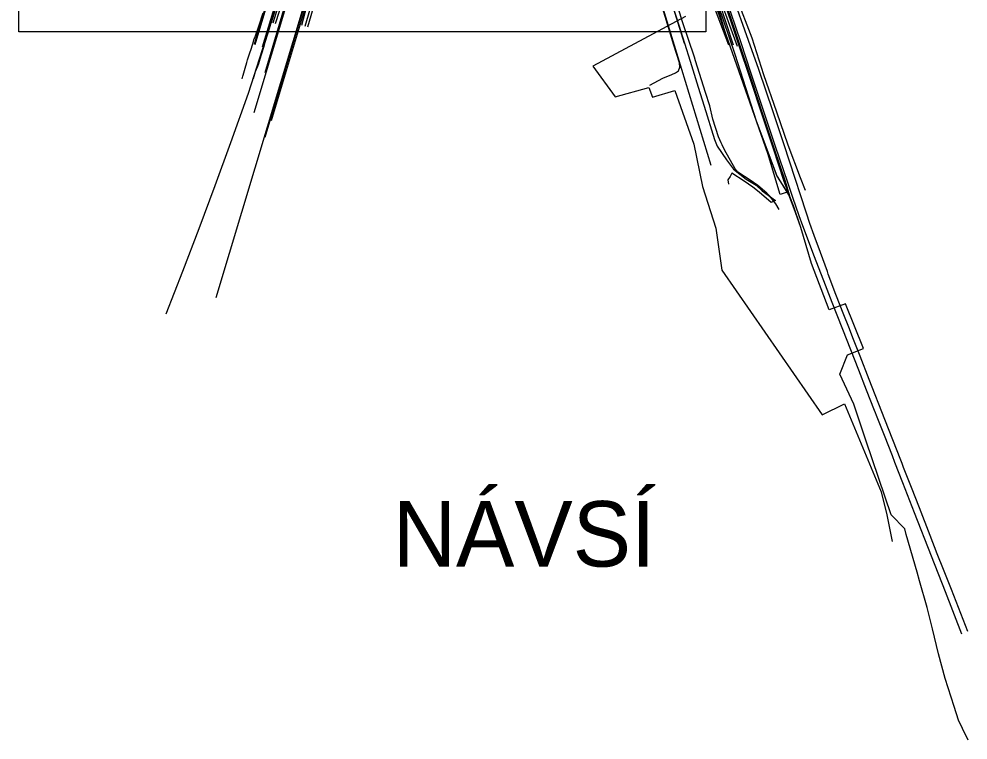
# Model space of a CAD drawing. Extents: x -439827 to -439102, y -1131353 to -1129707.
# Drawn here: x -439827 to -439102, y -1131353 to -1130802 of the extents above; entities that cross this region are included whole.
import ezdxf

# ---------------------------------------------------------------- set-up
doc = ezdxf.new("R2010")
doc.units = 0
for name, color, linetype in [('Vrstva 1', 7, 'Continuous'), ('Vrstva 11', 7, 'Continuous'), ('Vrstva 20', 7, 'Continuous'), ('Vrstva 23', 7, 'Continuous'), ('Vrstva 34', 7, 'Continuous'), ('Vrstva 4', 7, 'Continuous'), ('Vrstva 5', 7, 'Continuous'), ('Vrstva 52', 7, 'Continuous'), ('Vrstva 57', 7, 'Continuous'), ('Vrstva 59', 7, 'Continuous'), ('Vrstva 63', 7, 'Continuous'), ('Vrstva 9', 7, 'Continuous')]:
    doc.layers.add(name, color=color, linetype=linetype)

msp = doc.modelspace()

# ---------------------------------------------------------------- linework, layer by layer
at = {"layer": 'Vrstva 1'}
msp.add_lwpolyline([(-439827.03, -1130069.63), (-439302.03, -1130069.63), (-439302.03, -1130812.13), (-439827.03, -1130812.13)], close=True, dxfattribs=at)
at = {"layer": 'Vrstva 11'}
for points in [[(-439344.75, -1130853.04), (-439334.81, -1130847.64), (-439327.91, -1130844.88), (-439325.14, -1130843.49), (-439322.82, -1130841.93), (-439321.71, -1130839.17), (-439322.18, -1130835.79), (-439326.59, -1130821.58), (-439331.18, -1130806.33), (-439334.82, -1130794.63), (-439341.65, -1130772.25), (-439347.37, -1130754.14), (-439353.24, -1130735.38), (-439356.7, -1130724.07), (-439358.88, -1130721.3), (-439364.23, -1130721.5)], [(-439327.41, -1130792.13), (-439322.68, -1130807.07), (-439318.32, -1130820.97), (-439314.01, -1130834.57), (-439307.87, -1130854.41), (-439303.31, -1130869.12), (-439295.3, -1130894.58), (-439293.28, -1130899.6), (-439286.23, -1130909.99), (-439280.74, -1130917.07), (-439271.1, -1130924.86), (-439263.44, -1130929.41), (-439258.82, -1130933.64), (-439248.69, -1130941.16), (-439251.96, -1130942.7), (-439261.16, -1130934.64), (-439265.96, -1130930.97), (-439272.69, -1130926.31), (-439281.98, -1130920.15), (-439283.47, -1130922.78), (-439285.1, -1130925.34), (-439284.68, -1130928.58)]]:
    msp.add_lwpolyline(points, dxfattribs=at)
at = {"layer": 'Vrstva 20'}
for points in [[(-439101.69, -1131270.51), (-439114.23, -1131238.44), (-439120.3, -1131222.99), (-439125.01, -1131210.96), (-439130.51, -1131196.96), (-439138.74, -1131175.97), (-439144.8, -1131160.49), (-439150.85, -1131145), (-439151.94, -1131142.17), (-439153.01, -1131139.41), (-439159.09, -1131123.91), (-439165.17, -1131108.4), (-439177.12, -1131077.83), (-439184.09, -1131059.99), (-439189.02, -1131047.41), (-439192.73, -1131037.87), (-439196.45, -1131028.35), (-439202.51, -1131012.87), (-439208.33, -1130997.31), (-439209.05, -1130995.41), (-439214.41, -1130980.93), (-439219.07, -1130967.95), (-439222.33, -1130958.57), (-439224.99, -1130950.73), (-439229.67, -1130936.76), (-439233.48, -1130925.08), (-439242.37, -1130897.89), (-439250.56, -1130873.22), (-439261.5, -1130841.02), (-439269.22, -1130818.81), (-439281.81, -1130783.4)], [(-439106.19, -1131272.38), (-439118.8, -1131240.08), (-439129.41, -1131212.96), (-439142.34, -1131179.87), (-439151.36, -1131156.8), (-439157.43, -1131141.25), (-439159.38, -1131136.29), (-439165.46, -1131120.77), (-439171.54, -1131105.25), (-439172.27, -1131103.41), (-439173.03, -1131101.51), (-439179.07, -1131086.07), (-439185.12, -1131070.62), (-439191.16, -1131055.14), (-439197.22, -1131039.65), (-439205.26, -1131019.08), (-439211.76, -1131002.46), (-439219.35, -1130982.8), (-439224.22, -1130969.9), (-439227.72, -1130960.4), (-439230.5, -1130952.68), (-439235.43, -1130938.74), (-439239.38, -1130927.29), (-439248.62, -1130899.93), (-439256.79, -1130875.39), (-439267.43, -1130843.28), (-439274.97, -1130820.59), (-439286.85, -1130785.13)], [(-439714.55, -1131027.76), (-439701.81, -1130994.99), (-439689.24, -1130962.45), (-439676.99, -1130929.7), (-439664.96, -1130896.87), (-439651.63, -1130859.05), (-439640.83, -1130825.79), (-439630.58, -1130792.29)]]:
    msp.add_lwpolyline(points, dxfattribs=at)
at = {"layer": 'Vrstva 23'}
msp.add_line((-439607.7, -1130788.1), (-439639.13, -1130892.85), dxfattribs=at)
at = {"layer": 'Vrstva 34'}
for p, q in [((-439297.84, -1130914.25), (-439362.76, -1130701.78)), ((-439318.14, -1130821.18), (-439355.89, -1130700.43))]:
    msp.add_line(p, q, dxfattribs=at)
at = {"layer": 'Vrstva 4'}
for points in [[(-439237.66, -1130937.67), (-439241.95, -1130926.67), (-439250.19, -1130901.72), (-439259.02, -1130875.53), (-439267.63, -1130849.51), (-439276.91, -1130821.49), (-439290.19, -1130781.67), (-439298.76, -1130756.05), (-439310.47, -1130722.55), (-439322.95, -1130685.21)], [(-439237.66, -1130937.67), (-439241, -1130926.51), (-439249.72, -1130901.17), (-439258.41, -1130875.05), (-439266.76, -1130849.35), (-439276.35, -1130820.73), (-439289.27, -1130782.25), (-439298.28, -1130755.54), (-439309.97, -1130722.04), (-439322.37, -1130684.93)]]:
    msp.add_lwpolyline(points, dxfattribs=at)
at = {"layer": 'Vrstva 5'}
msp.add_lwpolyline([(-439277.8, -1130823.31), (-439296.36, -1130772.17), (-439314.65, -1130718.28), (-439334.21, -1130661.63), (-439352.88, -1130603.99)], dxfattribs=at)
at = {"layer": 'Vrstva 52'}
for p, q in [((-439569.99, -1130615.42), (-439647.56, -1130873.99)), ((-439570.71, -1130615.21), (-439639.19, -1130843.47)), ((-439596.77, -1130755.14), (-439634.33, -1130880.34)), ((-439604.15, -1130774.51), (-439676.43, -1131015.48)), ((-439320.01, -1130803.69), (-439328.04, -1130777.27)), ((-439647.07, -1130821.71), (-439637.19, -1130789.29)), ((-439646.59, -1130821.86), (-439636.71, -1130789.43)), ((-439628.37, -1130786.09), (-439634.18, -1130805.23)), ((-439627.07, -1130786.48), (-439633.06, -1130805.57)), ((-439625.02, -1130787.1), (-439631.3, -1130806.09)), ((-439605.96, -1130788.01), (-439611.15, -1130807.34)), ((-439602.98, -1130788.91), (-439608.51, -1130808.13)), ((-439600.78, -1130789.57), (-439606.58, -1130808.71)), ((-439640.85, -1130823.61), (-439630.97, -1130791.18)), ((-439640.37, -1130823.75), (-439630.49, -1130791.33)), ((-439319.51, -1130805.36), (-439320.01, -1130803.69)), ((-439310.65, -1130831.44), (-439319.51, -1130805.36)), ((-439309.82, -1130834.38), (-439310.65, -1130831.44)), ((-439302.26, -1130858.49), (-439309.82, -1130834.38)), ((-439298.88, -1130868.88), (-439302.26, -1130858.49)), ((-439296.73, -1130878.83), (-439298.88, -1130868.88)), ((-439292.4, -1130892.32), (-439296.73, -1130878.83)), ((-439290.31, -1130897.08), (-439292.4, -1130892.32)), ((-439289.48, -1130898.64), (-439290.31, -1130897.08)), ((-439287.59, -1130902.27), (-439289.48, -1130898.64)), ((-439279.65, -1130916.85), (-439287.59, -1130902.27)), ((-439277.58, -1130919.37), (-439279.65, -1130916.85)), ((-439268.19, -1130925.58), (-439277.58, -1130919.37)), ((-439262.2, -1130929.67), (-439268.19, -1130925.58)), ((-439255.29, -1130935.4), (-439262.2, -1130929.67)), ((-439253.19, -1130937.5), (-439255.29, -1130935.4)), ((-439248.34, -1130943.52), (-439253.19, -1130937.5)), ((-439245.85, -1130947.95), (-439248.34, -1130943.52))]:
    msp.add_line(p, q, dxfattribs=at)
for points in [[(-439656.32, -1130848.09), (-439655.86, -1130846.15), (-439655.66, -1130845.24), (-439654.21, -1130839.86), (-439652.88, -1130835.67), (-439652.25, -1130833.68), (-439650.29, -1130827.51), (-439649.87, -1130826.19), (-439648.32, -1130821.33), (-439647.12, -1130817.62), (-439646.8, -1130816.7), (-439643.52, -1130807.24), (-439640.25, -1130797.78)], [(-439647.73, -1130847.87), (-439646.2, -1130842.47), (-439644.51, -1130838.36), (-439643.72, -1130836.41), (-439641.76, -1130830.17), (-439641.35, -1130828.83), (-439639.88, -1130823.9), (-439638.81, -1130820.15), (-439638.53, -1130819.22), (-439635.62, -1130809.65), (-439632.7, -1130800.08)]]:
    msp.add_lwpolyline(points, dxfattribs=at)
at = {"layer": 'Vrstva 57'}
for p, q in [((-439317.43, -1130800.51), (-439388.39, -1130838.33)), ((-439388.39, -1130838.33), (-439371.22, -1130861.88)), ((-439371.22, -1130861.88), (-439345.46, -1130854.66)), ((-439345.46, -1130854.66), (-439342.85, -1130862.13)), ((-439342.85, -1130862.13), (-439325.58, -1130857.02)), ((-439325.58, -1130857.02), (-439311.11, -1130898.02)), ((-439311.11, -1130898.02), (-439304.42, -1130930.43)), ((-439304.42, -1130930.43), (-439294.29, -1130962.32)), ((-439294.29, -1130962.32), (-439289.68, -1130994.43)), ((-439289.68, -1130994.43), (-439213, -1131104.89)), ((-439213, -1131104.89), (-439195.98, -1131096.54)), ((-439195.98, -1131096.54), (-439167.83, -1131163.72)), ((-439167.83, -1131163.72), (-439163.65, -1131181.31)), ((-439163.65, -1131181.31), (-439159.62, -1131201.58))]:
    msp.add_line(p, q, dxfattribs=at)
at = {"layer": 'Vrstva 59'}
msp.add_lwpolyline([(-439240.62, -1130935.08), (-439245.01, -1130936.58), (-439254.48, -1130905.19), (-439274.83, -1130847.06), (-439298.03, -1130780.81), (-439307.77, -1130752.97), (-439314.37, -1130732.15), (-439325.76, -1130696.24), (-439342.93, -1130644.21), (-439353.37, -1130615.72)], dxfattribs=at)
at = {"layer": 'Vrstva 63'}
for points in [[(-439229.71, -1130961.08), (-439234.32, -1130947.46), (-439238.47, -1130936.84), (-439247.92, -1130921.56), (-439263.26, -1130880.52), (-439279.45, -1130829.6), (-439292.59, -1130791.38), (-439307.55, -1130752.88), (-439315.73, -1130727.35), (-439322.67, -1130704.55), (-439333.32, -1130672.27), (-439337.22, -1130661.2)], [(-439101.53, -1131353.33), (-439105.73, -1131344.49), (-439108.88, -1131338.21), (-439112.01, -1131327.74), (-439119.01, -1131306.36), (-439124.02, -1131287.5), (-439128.69, -1131268.37), (-439132.78, -1131251.99), (-439138.57, -1131231.74), (-439140.5, -1131224.98), (-439148.76, -1131196.19), (-439149.94, -1131191.88), (-439160.28, -1131181.3), (-439179.34, -1131124.87), (-439188.82, -1131096.82), (-439199.62, -1131073.67), (-439193.71, -1131059), (-439181.44, -1131054.12), (-439195.14, -1131019.95), (-439207.65, -1131024.63), (-439221.22, -1130989.16), (-439229.39, -1130961.8), (-439235.02, -1130945.13), (-439238.36, -1130936.75), (-439247.52, -1130922.52), (-439263.24, -1130880.51), (-439279.55, -1130829.63), (-439292.52, -1130791.32)]]:
    msp.add_lwpolyline(points, dxfattribs=at)
at = {"layer": 'Vrstva 9'}
for points in [[(-439225.73, -1130933.4), (-439229.6, -1130923.89), (-439239.09, -1130898.92), (-439247.79, -1130873.56), (-439257.61, -1130845.04), (-439266.65, -1130817.15), (-439278.57, -1130785.62), (-439289.83, -1130752.46), (-439300.56, -1130719.61), (-439315.2, -1130678.17)], [(-439323.84, -1130689.38), (-439321.25, -1130700.45), (-439312.68, -1130723.16), (-439304.27, -1130748.72), (-439291.72, -1130789.56), (-439280.96, -1130822.04)], [(-439284.42, -1130822.41), (-439293.46, -1130790.12), (-439308.93, -1130748.79), (-439315.43, -1130723.82), (-439325.34, -1130701.43)], [(-439284.42, -1130822.41), (-439296.5, -1130790.25), (-439310.21, -1130749.66), (-439317.23, -1130725.23), (-439325.34, -1130701.43)]]:
    msp.add_lwpolyline(points, dxfattribs=at)

# ---------------------------------------------------------------- texts
at = {"layer": 'Vrstva 1'}
msp.add_text('NÁVSÍ', height=50, dxfattribs=at).set_placement((-439541.22, -1131220.79))

doc.saveas('drawing.dxf')
